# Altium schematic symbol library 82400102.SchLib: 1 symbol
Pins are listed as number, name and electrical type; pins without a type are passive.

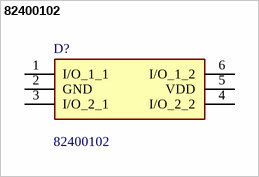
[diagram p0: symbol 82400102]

## 82400102
designator D?
TVS Diode Array WE-TVS SOT23-6L; 5Vdc; 2pF; 2Channel + VDD; Marking: .W00XY; Manufacturer_Name: Wurth Elektronik; Geometry.Height: 1.16mm
footprint SOT95P280X116-6N
pins: 1 I/O_1_1, 2 GND, 3 I/O_2_1, 4 I/O_2_2, 5 VDD, 6 I/O_1_2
